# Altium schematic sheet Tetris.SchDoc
size B; DocumentNumber: 1; SheetNumber: 1; SheetTotal: 1
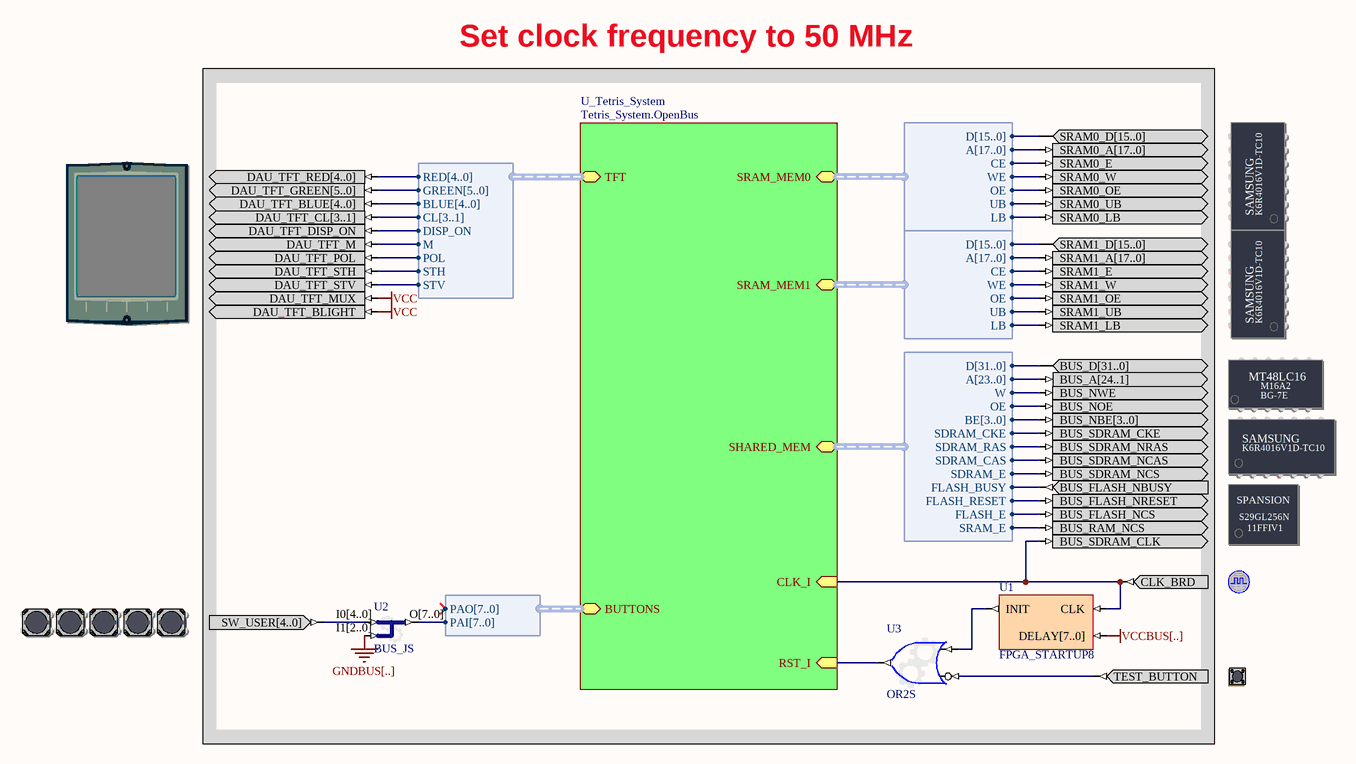
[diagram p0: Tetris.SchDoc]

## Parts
(Parts that share a designator on the sheet are numbered #1, #2 ... from top to bottom, then left to right.)
?#1  SRAM_DAUGHTER0  (value not drawn)
?#2  TFT_LCD  (value not drawn)
?#3  SRAM_DAUGHTER1  (value not drawn)
?#4  SHARED_MEM_DAUGHTER  (value not drawn)
?#5  CLOCK_BOARD  (value not drawn)
?#6  USER_BUTTONS  (value not drawn)
?#7  TEST_BUTTON  (value not drawn)
U1  FPGA_STARTUP8
U2  BUS_JS
U3  OR2S

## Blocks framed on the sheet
Set clock frequency to 50 MHz: ?#1-?#7 U1-U3

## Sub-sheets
U_Tetris_System = Tetris_System.OpenBus: CLK_I (in), RST_I (in), BUTTONS (harness WB_PRTIO_IO_1_1), TFT (harness VGA32_TFT), SRAM_MEM0 (harness WB_MEM_CTRL_SRAM16_A18), SRAM_MEM1 (harness WB_MEM_CTRL_SRAM16_A18), SHARED_MEM (harness WB_SHARED_MEM_CTRL)

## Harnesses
VGA32_TFT: RED[4..0], GREEN[5..0], BLUE[4..0], CL[3..1], DISP_ON, M, POL, STH, STV
WB_PRTIO_IO_1_1: PAO[7..0], PAI[7..0]
WB_MEM_CTRL_SRAM16_A18: D[15..0], A[17..0], CE, WE, OE, UB, LB
WB_SHARED_MEM_CTRL: D[31..0], A[23..0], W, OE, BE[3..0], SDRAM_CKE, SDRAM_RAS, SDRAM_CAS, SDRAM_E, FLASH_BUSY, FLASH_RESET, FLASH_E, SRAM_E

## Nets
GNDBUS[..]: U2.I1[2..0]
VCC: ?#2.DAU_TFT_BLIGHT ?#2.DAU_TFT_MUX
VCCBUS[..]: U1.DELAY[7..0]
Net?#1_SRAM0_E: ?#1.SRAM0_E ; sheet U_Tetris_System/SRAM_MEM0.CE
Net?#1_SRAM0_LB: ?#1.SRAM0_LB ; sheet U_Tetris_System/SRAM_MEM0.LB
Net?#1_SRAM0_OE: ?#1.SRAM0_OE ; sheet U_Tetris_System/SRAM_MEM0.OE
Net?#1_SRAM0_UB: ?#1.SRAM0_UB ; sheet U_Tetris_System/SRAM_MEM0.UB
Net?#1_SRAM0_W: ?#1.SRAM0_W ; sheet U_Tetris_System/SRAM_MEM0.WE
Net?#2_DAU_TFT_DISP_ON: ?#2.DAU_TFT_DISP_ON ; sheet U_Tetris_System/TFT.DISP_ON
Net?#2_DAU_TFT_M: ?#2.DAU_TFT_M ; sheet U_Tetris_System/TFT.M
Net?#2_DAU_TFT_POL: ?#2.DAU_TFT_POL ; sheet U_Tetris_System/TFT.POL
Net?#2_DAU_TFT_STH: ?#2.DAU_TFT_STH ; sheet U_Tetris_System/TFT.STH
Net?#2_DAU_TFT_STV: ?#2.DAU_TFT_STV ; sheet U_Tetris_System/TFT.STV
Net?#3_SRAM1_E: ?#3.SRAM1_E ; sheet U_Tetris_System/SRAM_MEM1.CE
Net?#3_SRAM1_LB: ?#3.SRAM1_LB ; sheet U_Tetris_System/SRAM_MEM1.LB
Net?#3_SRAM1_OE: ?#3.SRAM1_OE ; sheet U_Tetris_System/SRAM_MEM1.OE
Net?#3_SRAM1_UB: ?#3.SRAM1_UB ; sheet U_Tetris_System/SRAM_MEM1.UB
Net?#3_SRAM1_W: ?#3.SRAM1_W ; sheet U_Tetris_System/SRAM_MEM1.WE
Net?#4_BUS_FLASH_NBUSY: ?#4.BUS_FLASH_NBUSY ; sheet U_Tetris_System/SHARED_MEM.FLASH_BUSY
Net?#4_BUS_FLASH_NCS: ?#4.BUS_FLASH_NCS ; sheet U_Tetris_System/SHARED_MEM.FLASH_E
Net?#4_BUS_FLASH_NRESET: ?#4.BUS_FLASH_NRESET ; sheet U_Tetris_System/SHARED_MEM.FLASH_RESET
Net?#4_BUS_NOE: ?#4.BUS_NOE ; sheet U_Tetris_System/SHARED_MEM.OE
Net?#4_BUS_NWE: ?#4.BUS_NWE ; sheet U_Tetris_System/SHARED_MEM.W
Net?#4_BUS_RAM_NCS: ?#4.BUS_RAM_NCS ; sheet U_Tetris_System/SHARED_MEM.SRAM_E
Net?#4_BUS_SDRAM_CKE: ?#4.BUS_SDRAM_CKE ; sheet U_Tetris_System/SHARED_MEM.SDRAM_CKE
Net?#4_BUS_SDRAM_CLK: ?#4.BUS_SDRAM_CLK ?#5.CLK_BRD U1.CLK ; sheet U_Tetris_System/CLK_I
Net?#4_BUS_SDRAM_NCAS: ?#4.BUS_SDRAM_NCAS ; sheet U_Tetris_System/SHARED_MEM.SDRAM_CAS
Net?#4_BUS_SDRAM_NCS: ?#4.BUS_SDRAM_NCS ; sheet U_Tetris_System/SHARED_MEM.SDRAM_E
Net?#4_BUS_SDRAM_NRAS: ?#4.BUS_SDRAM_NRAS ; sheet U_Tetris_System/SHARED_MEM.SDRAM_RAS
Net?#7_TEST_BUTTON: ?#7.TEST_BUTTON U3.I1
NetU1_INIT: U1.INIT U3.I0
NetU3_O: U3.O ; sheet U_Tetris_System/RST_I

Not connected (* = marked no-connect by the designer): ?#1 SRAM0_A[17..0] SRAM0_D[15..0]; ?#2 DAU_TFT_BLUE[4..0] DAU_TFT_CL[3..1] DAU_TFT_GREEN[5..0] DAU_TFT_RED[4..0]; ?#3 SRAM1_A[17..0] SRAM1_D[15..0]; ?#4 BUS_A[24..1] BUS_D[31..0] BUS_NBE[3..0]; ?#6 SW_USER[4..0]; U2 I0[4..0] O[7..0]

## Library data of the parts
?#1 = SRAM_DAUGHTER0: Free Static RAM - Daughterboard; PortComponent: True
?#2 = TFT_LCD: TFT LCD Panel; PortComponent: True
?#3 = SRAM_DAUGHTER1: Free Static RAM - Daughterboard; PortComponent: True
?#4 = SHARED_MEM_DAUGHTER: Shared Memory - Daughterboard; PortComponent: True
?#5 = CLOCK_BOARD: Global System Clock Supply; PortComponent: True
?#6 = USER_BUTTONS: Generic User Buttons; PortComponent: True
?#7 = TEST_BUTTON: Test / Reset Button; PortComponent: True
U1 = FPGA_STARTUP8: FPGA Startup With 8 Bit Delay
U2 = BUS_JS: Configurable Bus Joiner/Splitter; ConfiguratorName: GENERIC_BUS_JS; ConfigurationParameters: {}Version[1.0]{}SplitterJoinerType[Joiner]{}SignalCount[2]{}SignalWidth0[5]{}SignalWidth1[3]{}
U3 = GATE: Configurable Generic Gate; ConfiguratorName: GENERIC_GATE; ConfigurationParameters: {}Version[1.0]{}GateKind[OR]{}BusInput[False]{}GateInputType[Bit]{}GateOutputOption[Normal]{}BusWidth[8]{}RegisterOutputs[False]{}NegativeClockEdge[False]{}InputCount[2]{}InputInvert0[False]{}InputInvert1[True]{}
